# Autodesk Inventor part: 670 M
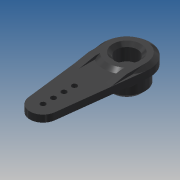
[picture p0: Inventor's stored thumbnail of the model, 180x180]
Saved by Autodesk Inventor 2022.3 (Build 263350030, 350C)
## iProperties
Created: 2021-08
Part Number: 670 M
Material: Nylon 6/6
Document SubType Name: Modeling
Designer: dotwibo2
Mass: 0.28903 g
Surface Area: 4.66998 cm^2
Volume: 0.255779 cm^3
Density: 1.13 g/cm^3
Appearance: Dark Gray
Description: SUPER STRENGTH LONG SERVO MEDIUM ARM
Vendor: DUBRO
UOFM: EACH
MAKE_OR_BUY: REF
PURCH_QTY: 0
BOM_MATL: -
Note: INCLUDED IN SET
Vendor Part No: 670 M
Alt_PN: DUBRO 670 M
Author: dotwibo2
Title: SUPER STRENGTH LONG SERVO MEDIUM ARM
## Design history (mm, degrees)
sketch "Sketch1"
  geometry: L1 (0, -7.52)-(0, 4.8) reference; L2 (1.65, -1.71)-(1.65, -2.76); L3 (1.65, -2.76)-(2.925, -2.76); L4 (2.925, -2.76)-(2.925, -5.76); L5 (2.925, -5.76)-(4.25, -5.76); L6 (5.5, -4.51)-(5.5, 0); L7 (5.5, 0)-(7.055, 0); L8 (7.055, 0)-(7.055, 2.1); L9 (7.055, 2.1)-(5.8, 3.04); L10 (5.8, 3.04)-(3.25, 3.04); L11 (-1.411, 0)-(8.466, 0) reference; L12 (1.65, -1.71)-(3.25, -1.71); L13 (3.25, -1.71)-(3.25, 3.04); L14 (5.5, -4.51)-(4.25, -5.76); 1 further point
  constraints: 25 end point, 5 horizontal, 5 vertical, 1 collinear
  dimensions: "d1" = 5.85 diameter of L4 L1; "d2" = 3.3 diameter of L2 L1; "d3" = 8.8 distance between parallel lines of L5 L10; "d7" = 11 diameter of L6 L1; "d9" = 5.76 distance between parallel lines of L7 L5; "d10" = 14.11 diameter of L8 L1; "d20" = 3 distance between parallel lines of L5 L3; "d48" = 6.5 diameter of L13 L1; "d49" = 4.75 distance between parallel lines of L10 L12; "d52" = 2.1 distance of L7.end L8.end; "d53" = 45 deg angle of L6 L14; "d54" = 8.5 diameter of L5.end L1; "d60" = 11.6 diameter of L9.end L1; "d66" = 0.94 vertical distance of L8.end L9.end (derived)
revolve "Revolution1" sketch "Sketch1" stored, may be unused: angle "d11" = 90 deg
sketch "Sketch3"
  geometry: L1 (-7.004, 0.849)-(-3.971, 25.881); L2 (3.971, 25.881)-(7.004, 0.849); L3 (9.877, 0)-(-9.877, 0) reference; L4 (0, -14.346)-(0, 36.691) reference; C1 r 7.055 at (0, 0) reference; A1 r 4 centre (0, 25.4) between (3.971, 25.881) and (-3.971, 25.881); A2 r 7.055 centre (0, 0) between (7.004, 0.849) and (-7.004, 0.849); 5 further points
  constraints: 4 end point, 4 point on circle, 3 point on line, 3 tangent, 2 centre point, 2 coincident, 1 concentric, 1 other
  dimensions: "d21" = 25.4 distance from line of L3 A1.centre; "d22" = 8 diameter of A1; "d23" = 9.525 distance of point (0, 15.875) A1.centre; "d29" = 3.175 distance of point (0, 25.4) point (0, 22.225); "d30" = 3.175 distance of point (0, 19.05) point (0, 22.225) (= d29)
extrude "Extrusion2" join sketch "Sketch3" distance "d27" = 2.1; taper "d28" = 0 deg
hole "Hole1" sketch "Sketch3" diameter "d31" = 1.5875; stored, may be unused: countersink angle "d35" = 90 deg, drill point angle "d37" = 118 deg; dims "d32" = 4, "d33" = 4, "d34" = 2, "d36" = 5
workplane "Work Plane1"
sketch "Sketch5"
  geometry: L1 (-5.265, 0)-(7.055, 0) reference; L2 (2.255, 0.849)-(2.255, -7.055) reference; L3 (2.255, 8.5)-(2.255, 0); L4 (2.255, 0)-(0.945, 0); L5 (0.945, 0)-(0.945, 4); L6 (0.945, 4)-(2.255, 8.5); L7 (5.295, 5.8)-(5.295, -5.8) reference; 1 further point
  constraints: 8 end point, 2 collinear, 2 vertical, 1 horizontal
  dimensions: "d55" = 4 distance of L4.end L5.end; "d56" = 8.5 distance from line of L1 L3.start; "d57" = 4.35 distance between parallel lines of L5 L7
extrude "Extrusion4" join sketch "Sketch5" distance "d58" = 1.72; taper "d59" = 0 deg
workplane "Work Plane2"
sketch "Sketch6"
  geometry: L1 (2.1, 25.881)-(2.1, 0.849) reference; L2 (-0.608, 0)-(3.648, 0) reference; L3 (2.1, 10.55)-(2.1, 0); L4 (2.1, 0)-(3.04, 0); L5 (3.04, 0)-(3.04, 5.8); L6 (3.04, 5.8)-(2.1, 10.55); L7 (3.04, 5.8)-(3.04, -5.8) reference; 1 further point
  constraints: 9 end point, 3 collinear, 2 vertical, 1 horizontal
  dimensions: "d62" = 5.8 distance from line of L2 L5.end; "d63" = 4.75 vertical distance of L5.end L3.start
extrude "Extrusion5" join sketch "Sketch6" distance "d64" = 2; taper "d65" = 0 deg
mirror "Mirror1"
chamfer "Chamfer1" distance "d67" = 1; stored, may be unused: second distance "d68" = 2, angle "d69" = 45 deg
body "Solid1"
other parameters: "d61" = 5.8 (= 0.5 x d60)
